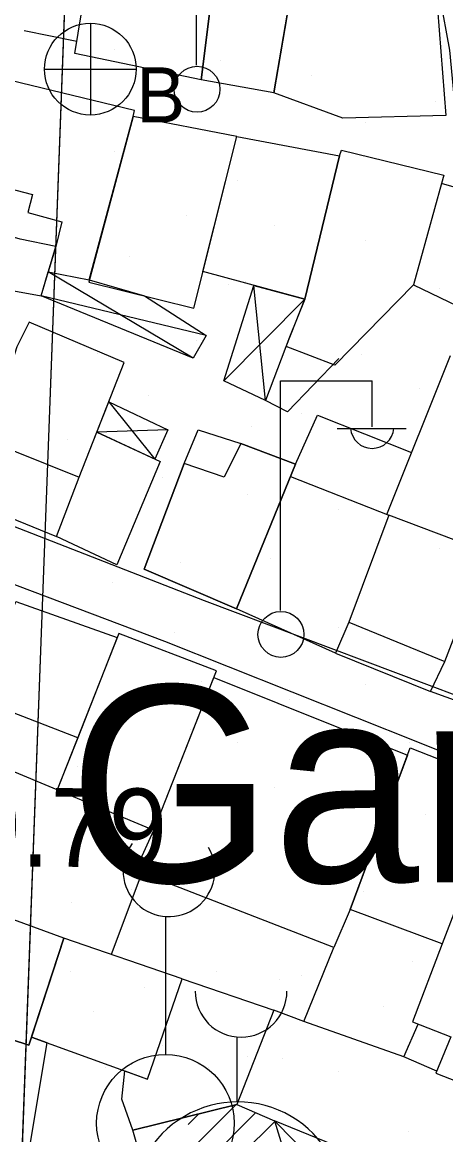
# Model space of a CAD drawing. Extents: x 417997 to 421451, y 4451742 to 4455216.
# Drawn here: x 419925.3 to 419957.6, y 4452433.3 to 4452518.2 of the extents above; entities that cross this region are included whole.
import ezdxf

# ---------------------------------------------------------------- set-up
doc = ezdxf.new("R2010")
doc.units = 0
for name, color, linetype in [('ADAKENARI', 7, 'Continuous'), ('B_Dini tesis', 7, 'Continuous'), ('B_Mesken', 7, 'Continuous'), ('B_Sundurma', 7, 'Continuous'), ('B_Tarama', 7, 'Continuous'), ('B_Teras', 7, 'Continuous'), ('Default', 7, 'Continuous'), ('PL_REKRASYON', 7, 'Continuous'), ('S_Cami_Mescid', 7, 'Continuous'), ('S_Elektrik_Diregi', 7, 'Continuous'), ('S_Minare', 7, 'Continuous'), ('S_Rogar_Kapagi_Buski', 7, 'Continuous'), ('Sinir_Duvar_tek_tarafa_ait', 7, 'Continuous'), ('TR_PARKALANI', 7, 'Continuous'), ('Y_Bucak_Koy', 7, 'Continuous'), ('Y_Kot_Noktasi', 7, 'Continuous'), ('Yol_Sose', 7, 'Continuous')]:
    doc.layers.add(name, color=color, linetype=linetype)

# ---------------------------------------------------------------- blocks, each defined once
blk = doc.blocks.new('POINT_DISPLAY')
at = {"layer": 'Default'}
blk.add_line((0, 0), (0, 0), dxfattribs=at)

msp = doc.modelspace()

# ---------------------------------------------------------------- linework, layer by layer
at = {"layer": 'ADAKENARI'}
for p, q in [((419929.094, 4452534.889), (419927.346, 4452487.893)), ((419929.094, 4452534.889), (419927.346, 4452487.893)), ((419927.346, 4452487.893), (419926.714, 4452470.9)), ((419927.346, 4452487.893), (419926.714, 4452470.9)), ((419926.714, 4452470.9), (419922.033, 4452345.065)), ((419926.714, 4452470.9), (419922.033, 4452345.065))]:
    msp.add_line(p, q, dxfattribs=at)
at = {"layer": 'B_Dini tesis'}
msp.add_lwpolyline([(419934.575, 4452430.7), (419933.744, 4452433.668), (419941.669, 4452435.619), (419944.556, 4452434.366), (419946.848, 4452426.903), (419948.69, 4452421.636), (419939.268, 4452418.859), (419936.703, 4452423.65)], close=True, dxfattribs=at)
at = {"layer": 'B_Mesken'}
for points in [[(419939.632, 4452519.233), (419938.965, 4452513.777), (419929.317, 4452515.768), (419930.327, 4452522.012), (419933.005, 4452528.512), (419937.307, 4452527.955), (419940.224, 4452527.578), (419940.065, 4452525.877)], [(419944.502, 4452512.766), (419938.965, 4452513.777), (419939.632, 4452519.233), (419939.817, 4452522.076), (419942.46, 4452522.067), (419946.03, 4452521.727)], [(419945.82, 4452520.497), (419957.003, 4452519.186), (419957.623, 4452511.05), (419949.773, 4452510.848), (419944.502, 4452512.766)], [(419922.227, 4452506.026), (419926.087, 4452505.022), (419925.712, 4452503.655), (419928.314, 4452502.945), (419927.866, 4452501.058), (419927.28, 4452499.115), (419930.412, 4452498.504), (419933.76, 4452510.961), (419933.859, 4452511.44), (419924.397, 4452513.706)], [(419933.76, 4452510.961), (419930.365, 4452498.329), (419938.387, 4452496.36), (419941.669, 4452509.435)], [(419941.669, 4452509.435), (419949.511, 4452507.972), (419946.875, 4452497.031), (419939.087, 4452499.148)], [(419949.511, 4452507.972), (419949.672, 4452508.402), (419957.469, 4452506.487), (419957.305, 4452505.854), (419955.166, 4452498.142), (419949.147, 4452492.007), (419945.43, 4452493.437), (419946.875, 4452497.031)], [(419955.166, 4452498.142), (419960.498, 4452495.564), (419963.665, 4452504.019), (419957.305, 4452505.854)], [(419924.08, 4452497.77), (419926.734, 4452497.304), (419927.866, 4452501.058), (419925.131, 4452501.617), (419920.028, 4452503.092), (419919.69, 4452502.517), (419918.545, 4452499.081)], [(419920.663, 4452481.885), (419927.899, 4452478.939), (419929.644, 4452483.466), (419933.076, 4452492.208), (419925.82, 4452495.278), (419924.874, 4452493.407), (419923.73, 4452489.777), (419922.335, 4452486.396)], [(419930.991, 4452486.896), (419935.816, 4452484.66), (419932.503, 4452476.782), (419927.899, 4452478.939), (419929.644, 4452483.466)], [(419937.644, 4452484.499), (419938.727, 4452487.081), (419941.987, 4452486.022), (419946.143, 4452484.443), (419941.645, 4452473.419), (419934.596, 4452476.435)], [(419949.205, 4452470.047), (419941.645, 4452473.419), (419945.767, 4452483.52), (419953.269, 4452480.575), (419950.236, 4452472.409)], [(419964.633, 4452465.805), (419964.187, 4452464.333), (419956.456, 4452467.124), (419957.546, 4452469.402), (419960.751, 4452477.737), (419962.411, 4452482.309), (419969.907, 4452479.334)], [(419950.236, 4452472.409), (419949.205, 4452470.047), (419956.456, 4452467.124), (419957.546, 4452469.402), (419960.751, 4452477.737), (419953.269, 4452480.575)], [(419927.964, 4452459.616), (419920.554, 4452462.683), (419920.84, 4452463.261), (419922.039, 4452466.493), (419924.815, 4452473.969), (419932.534, 4452471.236), (419929.529, 4452463.594)], [(419927.964, 4452459.616), (419935.339, 4452456.544), (419940.12, 4452468.702), (419932.656, 4452471.547)], [(419939.915, 4452468.18), (419954.702, 4452462.249), (419950.328, 4452450.5), (419949.087, 4452447.581), (419933.937, 4452453.477), (419935.339, 4452456.544)], [(419954.918, 4452462.831), (419962.036, 4452460.025), (419957.343, 4452447.875), (419950.328, 4452450.5)], [(419957.343, 4452447.875), (419955.085, 4452441.918), (419958.01, 4452440.778), (419956.881, 4452438.002), (419963.957, 4452435.228), (419971.875, 4452455.47), (419970.692, 4452455.976), (419970.761, 4452456.537), (419962.036, 4452460.025)], [(419915.681, 4452444.43), (419917.57, 4452443.641), (419918.644, 4452446.45), (419921.828, 4452445.291), (419920.549, 4452441.845), (419925.801, 4452440.145), (419928.478, 4452448.292), (419918.799, 4452451.849)], [(419925.997, 4452440.742), (419934.845, 4452437.55), (419937.501, 4452445.205), (419928.478, 4452448.292)], [(419933.744, 4452433.668), (419932.896, 4452436.022), (419933.116, 4452438.174), (419934.845, 4452437.55), (419937.501, 4452445.205), (419944.493, 4452442.813), (419941.669, 4452435.619)], [(419920.549, 4452441.845), (419918.49, 4452442.516), (419917.162, 4452438.198), (419919.033, 4452437.54), (419918.331, 4452434.363), (419925.832, 4452432.114), (419927.185, 4452440.314), (419925.997, 4452440.742), (419925.801, 4452440.145)]]:
    msp.add_lwpolyline(points, close=True, dxfattribs=at)
at = {"layer": 'B_Sundurma'}
for p, q in [((419938.335, 4452492.53), (419927.28, 4452499.115)), ((419943.852, 4452489.313), (419942.983, 4452498.089)), ((419939.347, 4452494.272), (419926.734, 4452497.304)), ((419940.688, 4452490.805), (419946.875, 4452497.031)), ((419931.898, 4452489.207), (419935.414, 4452484.847)), ((419936.411, 4452487.067), (419930.991, 4452486.896)), ((419953.175, 4452425.677), (419944.556, 4452434.366))]:
    msp.add_line(p, q, dxfattribs=at)
for points in [[(419934.621, 4452497.284), (419939.347, 4452494.272), (419938.335, 4452492.53), (419926.734, 4452497.304), (419927.28, 4452499.115), (419930.412, 4452498.504)], [(419945.695, 4452494.132), (419943.852, 4452489.313), (419940.688, 4452490.805), (419942.983, 4452498.089), (419946.875, 4452497.031)], [(419931.898, 4452489.207), (419936.411, 4452487.067), (419935.414, 4452484.847), (419930.991, 4452486.896)], [(419946.848, 4452426.903), (419953.175, 4452425.677), (419954.92, 4452430.161), (419944.556, 4452434.366)]]:
    msp.add_lwpolyline(points, close=True, dxfattribs=at)
at = {"layer": 'B_Tarama'}
for p, q in [((419935.067, 4452429.071), (419941.597, 4452435.601)), ((419935.559, 4452427.442), (419943.11, 4452434.993)), ((419937.972, 4452434.098), (419938.782, 4452434.908)), ((419942.093, 4452431.854), (419944.567, 4452434.329))]:
    msp.add_line(p, q, dxfattribs=at)
at = {"layer": 'B_Teras'}
for points in [[(419923.73, 4452489.777), (419922.335, 4452486.396), (419929.644, 4452483.466), (419933.076, 4452492.208), (419925.82, 4452495.278), (419924.874, 4452493.407)], [(419934.596, 4452476.435), (419941.645, 4452473.419), (419946.143, 4452484.443), (419941.987, 4452486.022), (419940.711, 4452483.476), (419937.644, 4452484.499)], [(419950.236, 4452472.409), (419957.546, 4452469.402), (419960.751, 4452477.737), (419953.269, 4452480.575)], [(419924.815, 4452473.969), (419932.534, 4452471.236), (419929.529, 4452463.594), (419922.039, 4452466.493)]]:
    msp.add_lwpolyline(points, close=True, dxfattribs=at)
at = {"layer": 'PL_REKRASYON'}
msp.add_lwpolyline([(419934.651, 4452684.289), (419933.208, 4452645.511), (419929.094, 4452534.889), (419927.346, 4452487.893), (419926.714, 4452470.9), (419922.033, 4452345.065)], dxfattribs=at)
msp.add_lwpolyline([(419934.651, 4452684.289), (419933.208, 4452645.511), (419929.094, 4452534.889), (419927.346, 4452487.893), (419926.714, 4452470.9), (419922.033, 4452345.065)], dxfattribs=at)
at = {"layer": 'S_Cami_Mescid'}
msp.add_line((419941.705, 4452435.813), (419941.705, 4452440.763), dxfattribs=at)
for centre, radius, start, end in [((419942, 4452444.251), 3.5, 180, 0), ((419941.743, 4452427.715), 8.097, 359.45576, 180.54424)]:
    msp.add_arc(centre, radius, start, end, dxfattribs=at)
at = {"layer": 'S_Elektrik_Diregi'}
for p, q in [((419938.599, 4452514.888), (419938.599, 4452532.388)), ((419945.003, 4452473.305), (419945.003, 4452490.805)), ((419945.003, 4452490.805), (419952.003, 4452490.805)), ((419952.003, 4452487.305), (419952.003, 4452490.805)), ((419949.343, 4452487.165), (419954.593, 4452487.165))]:
    msp.add_line(p, q, dxfattribs=at)
for centre in [(419938.635, 4452513.052), (419945.039, 4452471.469)]:
    msp.add_circle(centre, 1.75, dxfattribs=at)
msp.add_arc((419952.004, 4452487.318), 1.658, 184.83843, 355.14641, dxfattribs=at)
at = {"layer": 'S_Minare'}
msp.add_line((419936.221, 4452449.957), (419936.221, 4452439.435), dxfattribs=at)
msp.add_circle((419936.221, 4452434.185), 5.25, dxfattribs=at)
msp.add_arc((419936.493, 4452453.446), 3.5, 143.60214, 30.48893, dxfattribs=at)
at = {"layer": 'S_Rogar_Kapagi_Buski'}
for p, q in [((419930.492, 4452518.085), (419930.492, 4452511.085)), ((419926.992, 4452514.585), (419933.992, 4452514.585))]:
    msp.add_line(p, q, dxfattribs=at)
msp.add_circle((419930.492, 4452514.585), 3.5, dxfattribs=at)
at = {"layer": 'Sinir_Duvar_tek_tarafa_ait'}
for points in [[(419929.467, 4452516.695), (419925.451, 4452517.509)], [(419953.134, 4452480.628), (419957.989, 4452492.744)], [(419949.458, 4452492.514), (419945.545, 4452488.453), (419943.852, 4452489.313)], [(419946.143, 4452484.443), (419947.823, 4452488.186), (419955.02, 4452485.337)], [(419934.43, 4452453.286), (419932.076, 4452447.061)], [(419954.432, 4452439.252), (419946.788, 4452441.936), (419949.087, 4452447.581)], [(419946.788, 4452441.936), (419944.493, 4452442.813)], [(419956.943, 4452438.155), (419954.432, 4452439.252), (419955.531, 4452441.744)]]:
    msp.add_lwpolyline(points, dxfattribs=at)
at = {"layer": 'Yol_Sose'}
for points in [[(419945.91, 4452587.865), (419946.528, 4452583.904), (419948.351, 4452570.02), (419951.386, 4452548.477), (419954.961, 4452532.128), (419957.924, 4452516.032), (419958.444, 4452510.369), (419958.659, 4452507.893), (419959.122, 4452506.697), (419959.417, 4452506.156), (419981.261, 4452499.447), (419995.536, 4452495.704), (419999.371, 4452494.921), (420000.137, 4452494.377), (420000.89, 4452493.237), (420002.108, 4452488.156), (420003.721, 4452484.642), (420005.487, 4452482.446), (420016.724, 4452474.465)], [(420023.133, 4452441.098), (419997.965, 4452450.339), (419982.04, 4452456.881), (419961.12, 4452465.793), (419939.215, 4452474.037), (419921.495, 4452480.933)], [(419914.541, 4452472.896), (419916.625, 4452478.029), (419916.748, 4452478.122), (419917.056, 4452478.158), (419936.146, 4452470.967), (419955.59, 4452463.228), (419972.442, 4452456.447), (419972.781, 4452456.117), (419972.961, 4452455.581), (419972.594, 4452454.113), (419967.588, 4452441.903), (419960.402, 4452425.437), (419954.813, 4452409.959), (419954.352, 4452407.38), (419953.046, 4452400.331)]]:
    msp.add_lwpolyline(points, dxfattribs=at)

# ---------------------------------------------------------------- block references
at = {"layer": 'TR_PARKALANI', "xscale": 0.1, "yscale": 0.10000000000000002}
for p in [(419932.364, 4452516.105), (419932.364, 4452516.105), (419940.435, 4452515.243), (419940.435, 4452515.243), (419947.341, 4452514.118), (419947.341, 4452514.118), (419956.879, 4452512.15), (419956.879, 4452512.15), (419937.117, 4452511.353), (419937.117, 4452511.353), (419951.478, 4452510.545), (419951.478, 4452510.545), (419932.364, 4452508.303), (419932.364, 4452508.303), (419941.059, 4452507.153), (419941.059, 4452507.153), (419941.699, 4452506.11), (419941.699, 4452506.11), (419937.848, 4452503.402), (419937.848, 4452503.402), (419944.572, 4452502.644), (419944.572, 4452502.644), (419951.478, 4452501.52), (419951.478, 4452501.52), (419933.461, 4452500.295), (419933.461, 4452500.295), (419941.059, 4452498.128), (419941.059, 4452498.128), (419942.309, 4452498.392), (419942.309, 4452498.392), (419957.139, 4452497.868), (419957.139, 4452497.868), (419938.579, 4452493.898), (419938.579, 4452493.898), (419931.049, 4452492.874), (419931.049, 4452492.874), (419951.197, 4452492.81), (419951.197, 4452492.81), (419955.604, 4452490.218), (419955.604, 4452490.218), (419934.923, 4452489.694), (419934.923, 4452489.694), (419946.589, 4452488.357), (419946.589, 4452488.357), (419942.78, 4452487.322), (419942.78, 4452487.322), (419950.551, 4452486.769), (419950.551, 4452486.769), (419928.783, 4452486.299), (419928.783, 4452486.299), (419936.03, 4452483.408), (419936.03, 4452483.408), (419942.503, 4452482.149), (419942.503, 4452482.149), (419945.129, 4452482.033), (419945.129, 4452482.033), (419949.41, 4452481.024), (419949.41, 4452481.024), (419957.154, 4452477.99), (419957.154, 4452477.99), (419937.391, 4452476.99), (419937.391, 4452476.99), (419944.211, 4452477.265), (419944.211, 4452477.265), (419952.013, 4452477.265), (419952.013, 4452477.265), (419932.182, 4452475.437), (419932.182, 4452475.437), (419942.503, 4452473.123), (419942.503, 4452473.123), (419936.934, 4452471.598), (419936.934, 4452471.598), (419949.41, 4452471.998), (419949.41, 4452471.998), (419955.55, 4452470.354), (419955.55, 4452470.354), (419938.944, 4452467.851), (419938.944, 4452467.851), (419951.478, 4452467.674), (419951.478, 4452467.674), (419932.638, 4452466.663), (419932.638, 4452466.663), (419945.707, 4452466.481), (419945.707, 4452466.481), (419938.168, 4452464.196), (419938.168, 4452464.196), (419941.059, 4452464.282), (419941.059, 4452464.282), (419941.699, 4452463.238), (419941.699, 4452463.238), (419954.846, 4452463.19), (419954.846, 4452463.19), (419929.531, 4452461.363), (419929.531, 4452461.363), (419944.572, 4452459.773), (419944.572, 4452459.773), (419936.34, 4452458.987), (419936.34, 4452458.987), (419951.478, 4452458.648), (419951.478, 4452458.648), (419956.08, 4452457.707), (419956.08, 4452457.707), (419932.501, 4452455.879), (419932.501, 4452455.879), (419942.309, 4452455.52), (419942.309, 4452455.52), (419941.059, 4452455.256), (419941.059, 4452455.256), (419946.21, 4452454.051), (419946.21, 4452454.051), (419933.598, 4452452.041), (419933.598, 4452452.041), (419951.328, 4452451.858), (419951.328, 4452451.858), (419929.029, 4452451.036), (419929.029, 4452451.036), (419941.275, 4452450.944), (419941.275, 4452450.944), (419955.075, 4452446.557), (419955.075, 4452446.557), (419928.976, 4452445.755), (419928.976, 4452445.755), (419940.087, 4452445.755), (419940.087, 4452445.755), (419944.93, 4452445.187), (419944.93, 4452445.187), (419946.589, 4452445.486), (419946.589, 4452445.486), (419934.597, 4452444.508), (419934.597, 4452444.508), (419930.765, 4452442.719), (419930.765, 4452442.719), (419952.881, 4452443.085), (419952.881, 4452443.085), (419936.001, 4452440.093), (419936.001, 4452440.093), (419942.503, 4452439.277), (419942.503, 4452439.277), (419954.709, 4452440.069), (419954.709, 4452440.069), (419931.679, 4452438.424), (419931.679, 4452438.424), (419939.481, 4452438.424), (419939.481, 4452438.424), (419945.129, 4452439.161), (419945.129, 4452439.161), (419949.41, 4452438.152), (419949.41, 4452438.152), (419944.199, 4452433.58), (419944.199, 4452433.58), (419954.801, 4452433.58), (419954.801, 4452433.58)]:
    msp.add_blockref('POINT_DISPLAY', p, dxfattribs=at)

# ---------------------------------------------------------------- texts
at = {"layer": 'S_Rogar_Kapagi_Buski'}
msp.add_text('B', height=4.2, dxfattribs=at).set_placement((419933.992, 4452510.521))
at = {"layer": 'Y_Bucak_Koy'}
msp.add_text('Santral Garaj', height=15, dxfattribs=at).set_placement((419859.693, 4452452.568))
at = {"layer": 'Y_Kot_Noktasi'}
msp.add_text('129.79 ', height=6, rotation=359.61735, dxfattribs=at).set_placement((419911.792, 4452453.86))

doc.saveas('drawing.dxf')
